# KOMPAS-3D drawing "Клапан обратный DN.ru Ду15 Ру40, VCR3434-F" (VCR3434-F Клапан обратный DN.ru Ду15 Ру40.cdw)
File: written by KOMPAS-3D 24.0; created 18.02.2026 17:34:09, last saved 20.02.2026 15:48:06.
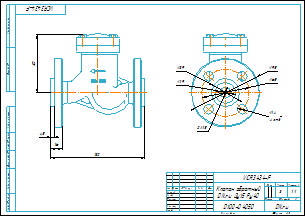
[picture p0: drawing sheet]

Document properties: art: D100-04050; Автор: R2D2; Форматы листов документа: A3; Полное имя файла: VCR3434-F Клапан обратный DN.ru Ду15 Ру40.m3d; Масса: 3; Наименование: Клапан обратный DN.ru Ду15 Ру40; Количество листов документа: 1; Примечание: D100-04050

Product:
- Part/product: Клапан обратный DN.ru Ду15 Ру40  | designation VCR3434-F
    Масса: 3
    Раздел спецификации: Прочие изделия
    Примечание: D100-04050
    additional columns: D100-04050

Views: Вид 1, Спереди, Проекционный вид 2
Referenced files in E:\Работа\Зайцев\VCR3434-F Клапан обратный DN.ru Ду15-300\DN15\: VCR3434-F Клапан обратный DN.ru Ду15 Ру40.m3d
Referenced files in E:\Работа\Зайцев\Для компаса\: чертеж DN.ru А3.cdt
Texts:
  VCR3434-F
  чертеж DN.ru А3.cdt
  Клапан обратный
  DN.ru Ду15 Ру40
  prop
  Клапан обратный DN.ru Ду15 Ру40
  VCR3434-F Клапан обратный DN.ru Ду15 Ру40
Dimensions and other numbers on the sheet: 0; 3; 2; 4; 95; 65; 39; 29; 15; 14; 4 отв.; 130; 80; 4,5; 16; 1:1; 1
